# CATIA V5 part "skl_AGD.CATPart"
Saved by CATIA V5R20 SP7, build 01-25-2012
Part number: skl_AGD
Publications: "Axe_ADG_A", "Axe_ADG_D", "Axe_ADG_G", "AD", "DG", "AG", "Point A", "Point G", "Point D", "Plan.1"
Bounding box of the stored display mesh (mm): x 0 to 20, y 0 to 83.1, z 0 to 59.286
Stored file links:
  U:\IAO-Thinkmotion\TRAVAIL A RENDRE\skl_AGD.CATPart
  U:\IAO-Thinkmotion\TRAVAIL A RENDRE\skl_levier2bras.CATProduct
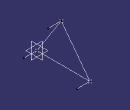
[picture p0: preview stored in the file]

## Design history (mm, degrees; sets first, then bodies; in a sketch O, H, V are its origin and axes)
Set1
  Point1 "Point A": linked copy from another document
  Point2 "Point G": linked copy from another document
  DatumPoint1 "Point D": linked copy from another document
  Plane1: linked copy from another document
Set2
  Line1 "AG": type PtPt, FirstPoint Point1, SecondPoint Point2
  Line2 "DG": type PtPt, FirstPoint DatumPoint1, SecondPoint Point2
  Line3 "AD": type PtPt, FirstPoint Point1, SecondPoint DatumPoint1
  Line4 "Axe_ADG_G": type Normal, RefPoint Point2, RefSkin Plane1, Start 0, End 20
  Line5 "Axe_ADG_D": type Normal, RefPoint DatumPoint1, RefSkin Plane1, Start 0, End 20
  Line6 "Axe_ADG_A": type Normal, RefPoint Point1, RefSkin Plane1, Start 0, End 20
Body1 (main body)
